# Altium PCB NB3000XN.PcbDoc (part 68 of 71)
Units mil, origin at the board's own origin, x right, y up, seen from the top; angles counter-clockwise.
Board outline 9527.56 x 6929.77 mil, 6 copper layers (Top Layer, GND+SHIELD, MidLayer1, MidLayer2, P2 - 3V3+5V0, Bottom Layer), stack 62.375 mil thick; 832 components, 1027 nets, 4655 pads, 4981 vias.
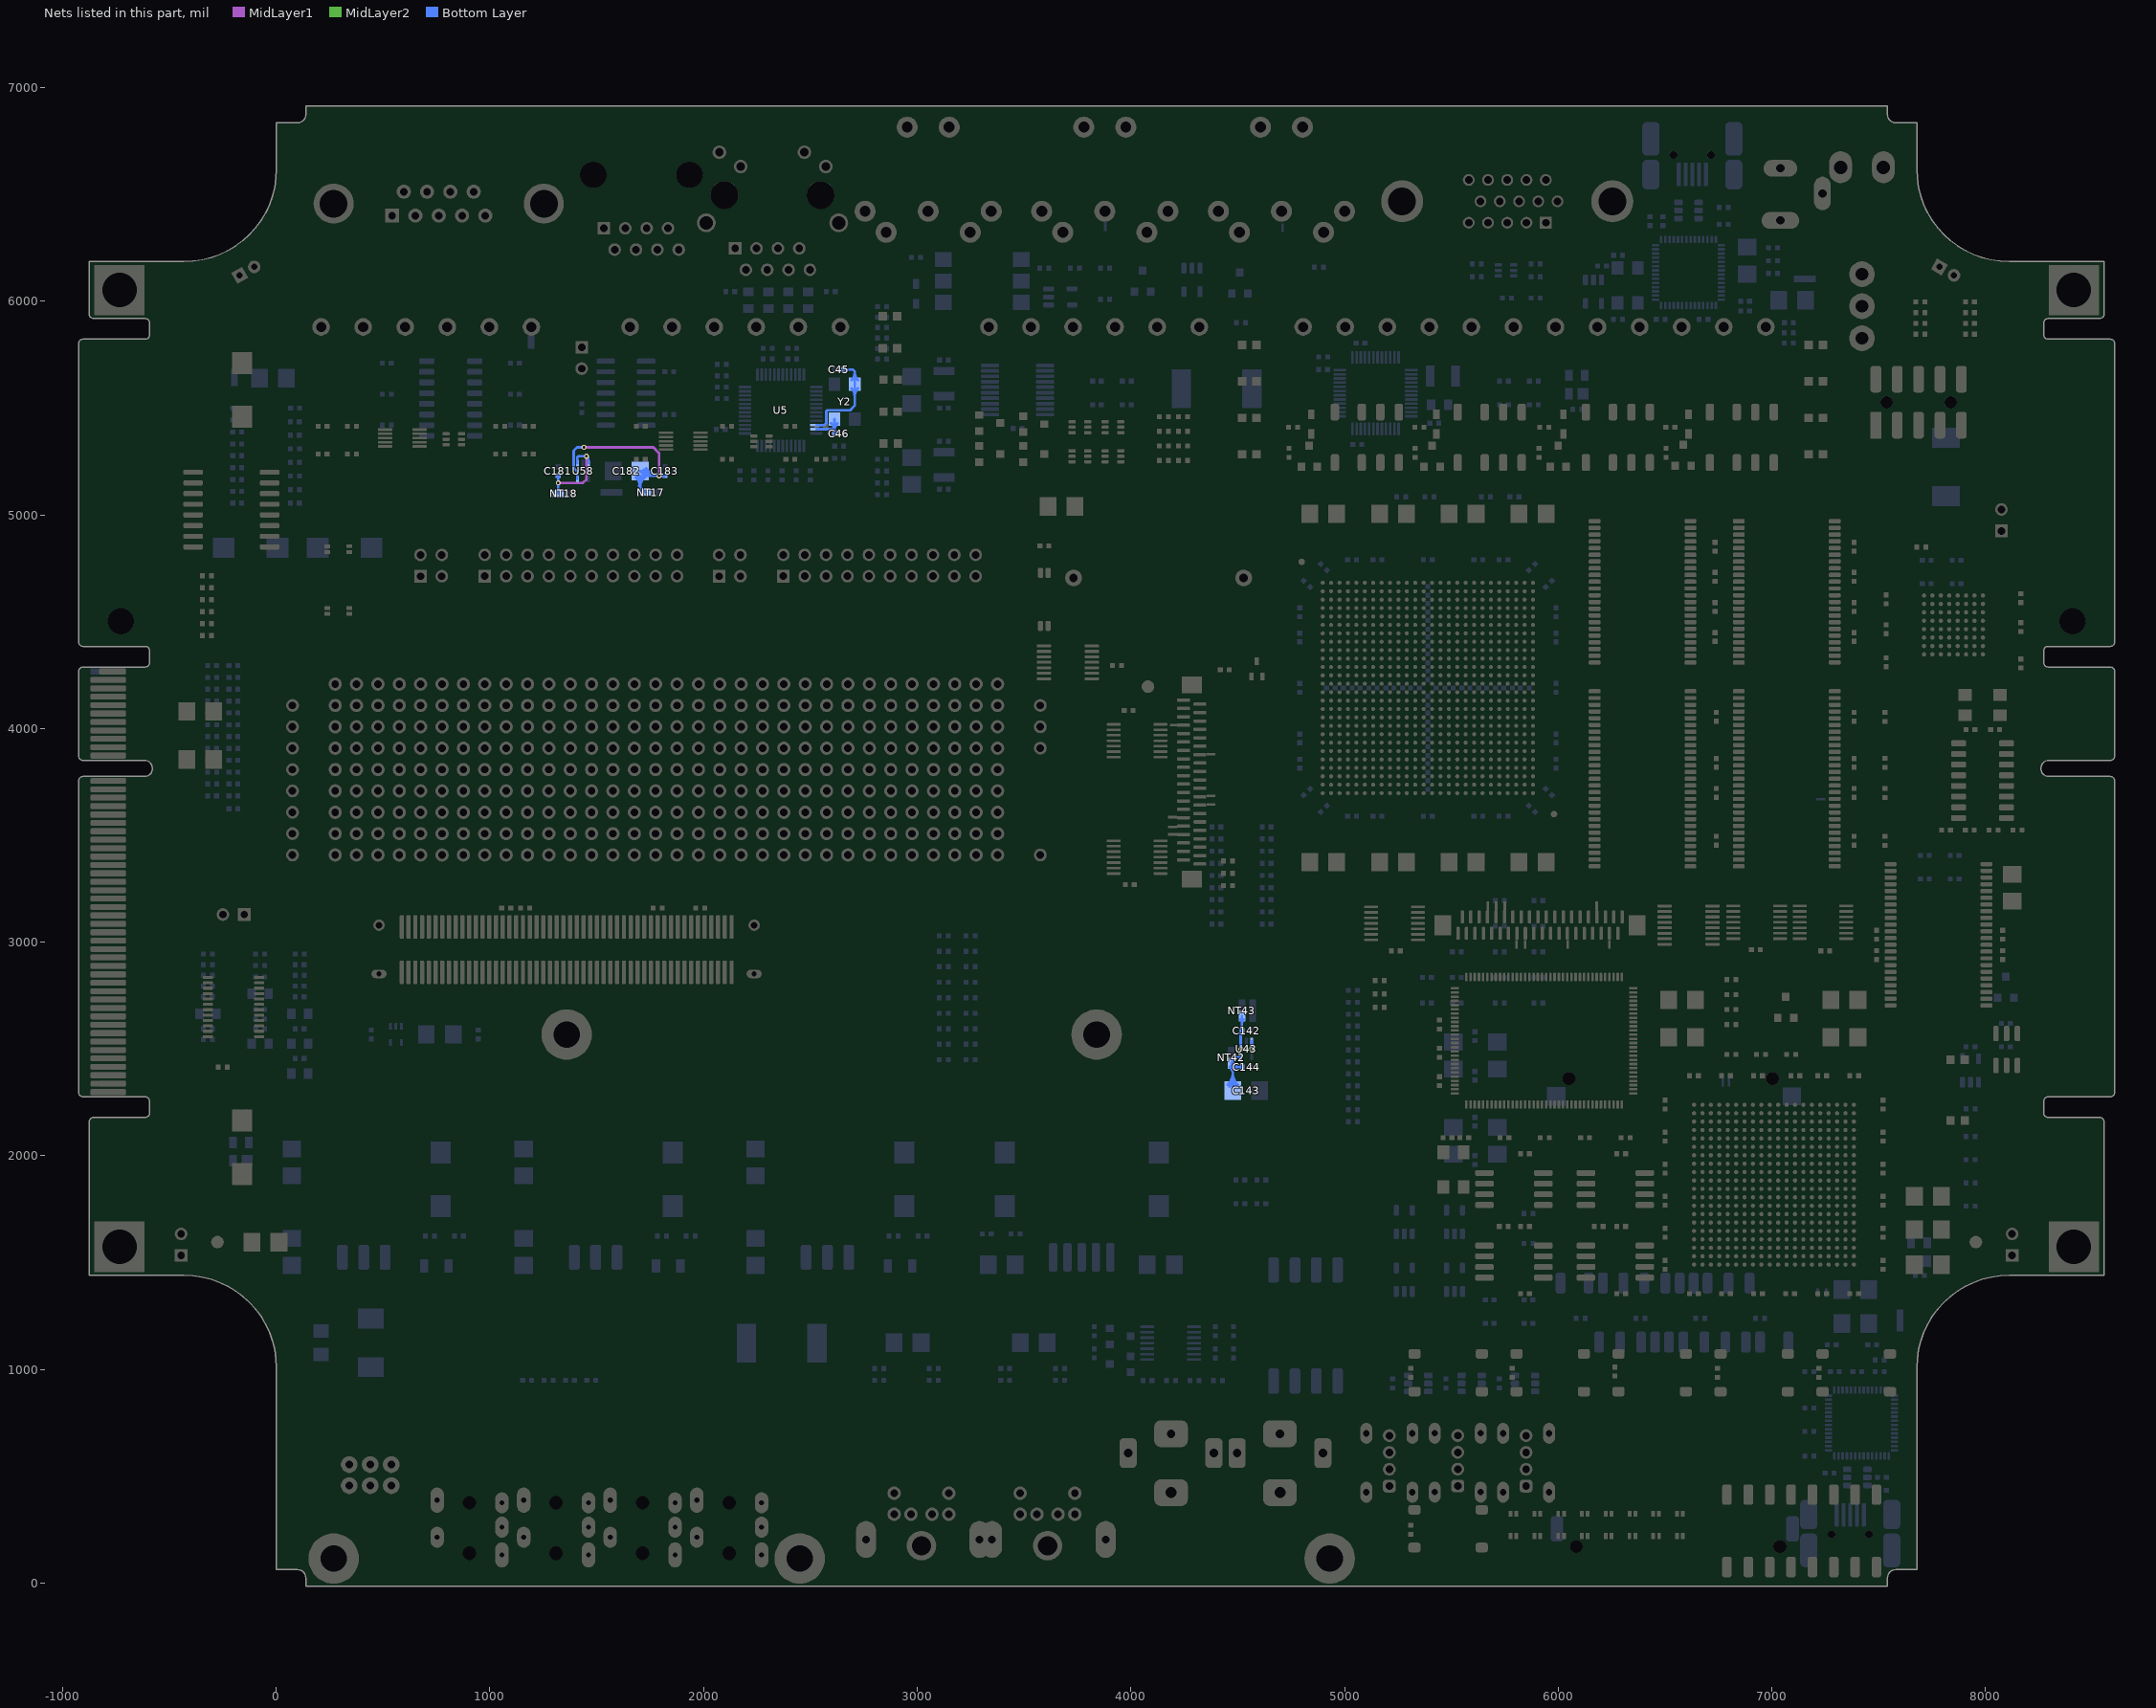
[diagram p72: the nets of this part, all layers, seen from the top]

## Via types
v1: diameter 23, hole 11.81, Top Layer to Bottom Layer, 3672 vias
v2: diameter 26, hole 11.81, Top Layer to Bottom Layer, 461 vias
v3: diameter 19, hole 11.81, Top Layer to Bottom Layer, tented both sides, 396 vias
v4: diameter 23.62, hole 11.81, Top Layer to Bottom Layer, 288 vias
v5: diameter 20, hole 11.81, Top Layer to Bottom Layer, 91 vias
v6: diameter 23, hole 11.81, Top Layer to Bottom Layer, tented both sides, 50 vias
v7: diameter 31, hole 11.81, Top Layer to Bottom Layer, 15 vias
v8: diameter 27.56, hole 11.81, Top Layer to Bottom Layer, tented both sides, 4 vias
v9: diameter 29, hole 11.81, Top Layer to Bottom Layer, 3 vias
v10: diameter 21, hole 11.81, Top Layer to Bottom Layer, 1 vias

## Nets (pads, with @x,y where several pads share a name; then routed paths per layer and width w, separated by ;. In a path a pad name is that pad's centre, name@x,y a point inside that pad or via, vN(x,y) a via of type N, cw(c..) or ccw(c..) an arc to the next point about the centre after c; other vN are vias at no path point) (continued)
VINA: C142.2 NT43.1 U43.1 U43.3 | length 405.5
  MidLayer2 w12: v1(4515.19,2500.04) v1(4565.19,2500.04) ; v1@4519.08,2496.15 cw(c4528.47,2486.76) 4528.47,2500.04 cw(c4528.47,2513.32) v1@4519.08,2503.93 ; v1@4561.3,2496.15 ccw(c4551.91,2486.76) 4551.91,2500.04 ccw(c4551.91,2513.32) v1@4561.3,2503.93
  Bottom Layer w12: NT43.1@4513.34,2637.78 cw(c4496.7,2621.14) 4520.24,2621.14 cw(c4543.77,2621.14) NT43.1@4527.13,2637.78 ; 4514.41,2515.2 ccw(c4530.35,2515.2) v1@4519.08,2503.93 ; 4514.41,2556.71 cw(c4548.6,2556.71) C142.2@4524.42,2580.89 ; v1(4515.19,2500.04) 4514.41,2500.82 U43.1@4514.41,2537.4 4514.41,2579.25 4520.24,2585.08 NT43.1@4520.24,2654.92 ; C142.2@4516.21,2589.11 ccw(c4506.48,2598.84) 4520.24,2598.84 ; 4520.24,2599.22 ccw(c4534.53,2599.22) C142.2@4524.42,2589.11 ; v1@4561.3,2503.93 ccw(c4550.95,2514.29) 4565.59,2514.29 ; v1@4565.59,2500.44 U43.3@4565.59,2537.4 ; 4565.59,2512.35 ccw(c4577.5,2512.35) v1@4569.08,2503.93
VINB: C181.2 NT18.1 U58.1 U58.3 | length 636.3
  MidLayer1 w12: v1(1319.92,5150.04) 1435.04,5150.04 1452.19,5167.19 v1(1452.19,5275.04) ; v1@1323.81,5146.15 cw(c1333.2,5136.76) 1333.2,5150.04 cw(c1333.2,5163.32) v1@1323.81,5153.93 ; v1@1448.3,5271.15 cw(c1438.91,5261.76) 1452.19,5261.76 cw(c1465.47,5261.76) v1@1456.08,5271.15
  Bottom Layer w12: NT18.1@1313.03,5106.66 ccw(c1296.2,5123.49) 1320,5123.49 ; C181.2@1315.89,5180.22 cw(c1305.97,5170.3) 1320,5170.3 cw(c1334.03,5170.3) C181.2@1324.11,5180.22 ; v1@1316.03,5146.15 cw(c1306.45,5136.57) 1320,5136.57 ; v1@1316.03,5153.93 ccw(c1306.45,5163.51) 1320,5163.51 ; NT18.1@1319.92,5099.76 1320,5099.84 1320,5150.04 C181.2@1320,5184.33 ; 1320,5123.11 ccw(c1343.27,5123.11) NT18.1@1326.81,5106.66 ; 1320,5136.95 cw(c1333.01,5136.95) v1@1323.81,5146.15 ; 1320,5163.13 ccw(c1333.01,5163.13) v1@1323.81,5153.93 ; U58.1@1409.41,5242.4 1409.41,5269.41 1415.04,5275.04 v1(1452.19,5275.04) 1460.59,5266.64 U58.3@1460.59,5242.4 ; v1@1448.3,5278.93 cw(c1438.91,5288.32) 1438.91,5275.04 cw(c1438.91,5261.76) 1448.3,5271.15 cw(c1418.63,5241.48) U58.3@1460.59,5241.48
VOUTA: C143.1 C144.2 NT42.2 U43.5 | length 639.8
  Bottom Layer w12: C143.1@4453.41,2332.53 ccw(c4396.45,2389.5) 4477.01,2389.5 ccw(c4557.57,2389.5) C143.1@4500.6,2332.53 ; C143.1@4461.9,2324.05 ccw(c4425.42,2360.53) 4477.01,2360.53 ccw(c4528.6,2360.53) C143.1@4492.12,2324.05 ; NT42.2@4462.87,2416.75 cw(c4428.74,2382.62) 4477.01,2382.62 ; NT42.2@4468.17,2422.05 ccw(c4485.2,2439.08) NT42.2@4485.2,2415 ; NT42.2@4470,2433.37 4488.37,2415 ; NT42.2@4471.29,2453.78 ccw(c4476.23,2484.83) 4498.46,2462.6 ; NT42.2@4473.11,2414.49 cw(c4479.73,2396.39) 4493.36,2410.02 ; NT42.2@4476.66,2430.54 ccw(c4514.17,2468.05) C144.2@4514.17,2415 ; C143.1@4477.01,2305 4477.01,2426.65 NT42.2@4469.76,2433.9 4498.46,2462.6 ; NT42.2@4479.51,2423.76 ccw(c4488.37,2423.86) 4488.37,2415 ; U43.5@4514.41,2462.6 4498.46,2462.6 ; C144.2@4516.21,2410.89 ccw(c4506.29,2400.97) 4506.29,2415 ccw(c4506.29,2429.03) C144.2@4516.21,2419.11 ; C144.2@4520.31,2415 4488.37,2415
VOUTB: C182.1 C183.2 NT17.2 U58.5 | length 1382.6
  MidLayer1 w12: v1(1440.19,5316.71) 1765.15,5316.71 1791.86,5290 v1(1791.86,5183.37) ; v1@1444.08,5312.82 cw(c1453.47,5303.43) 1453.47,5316.71 cw(c1453.47,5329.99) v1@1444.08,5320.6 ; v1@1787.97,5187.26 ccw(c1778.58,5196.65) 1791.86,5196.65 ccw(c1805.14,5196.65) v1@1795.75,5187.26
  Bottom Layer w12: U58.5@1409.41,5167.6 1409.41,5203.14 1392.52,5220.03 1392.52,5300.94 1408.29,5316.71 v1(1440.19,5316.71) ; v1@1436.3,5312.82 ccw(c1426.91,5303.43) 1426.91,5316.71 ccw(c1426.91,5329.99) v1@1436.3,5320.6 ; C182.1@1682.36,5175.23 cw(c1645.89,5130.65) 1703.48,5130.65 ; C182.1@1689.95,5184.52 cw(c1666.6,5155.97) 1703.48,5155.97 cw(c1740.37,5155.97) C182.1@1717.01,5184.52 ; 1698.36,5135.77 cw(c1672.38,5109.79) NT17.2@1708.94,5106.19 ; C182.1@1703.48,5183.37 1703.48,5130.65 ; C182.1@1703.48,5205 1724.15,5184.33 v1@1791.86,5184.33 ; C182.1@1711.52,5205.87 ccw(c1749.52,5228.61) 1749.52,5184.33 ; C182.1@1721.82,5212.04 ccw(c1770.69,5241.28) 1770.69,5184.33 ; C182.1@1724.61,5175.23 ccw(c1761.08,5130.65) 1703.48,5130.65 ; C182.1@1727.08,5177.47 cw(c1743.65,5160.9) 1743.65,5184.33 ; NT17.2@1728.9,5105.24 1703.48,5130.65 ; C182.1@1732.12,5218.2 ccw(c1791.85,5253.95) v1@1791.85,5184.33 ; 1776.27,5184.33 cw(c1776.27,5167.79) v1@1787.97,5179.49 ; v1@1795.75,5179.49 cw(c1807.44,5167.79) 1807.44,5184.33 ; C183.2@1815.89,5180.22 ccw(c1805.97,5170.3) 1805.97,5184.33 ccw(c1805.97,5198.36) C183.2@1815.89,5188.44 ; C183.2@1820,5184.33 v1@1791.86,5184.33
X1: C45.2 U5.46 Y2.1 | length 649.5
  Bottom Layer w12: U5.46@2528.19,5421.1 2566.1,5421.1 2575,5430 2575,5484.85 2580.15,5490 2685.85,5490 2707.5,5511.65 Y2.1@2707.5,5611.5 2707.5,5672 2699.5,5680 C45.2@2655.67,5680 ; C45.2@2659.78,5675.89 cw(c2669.7,5665.97) 2669.7,5680 cw(c2669.7,5694.03) C45.2@2659.78,5684.11 ; Y2.1@2692.3,5592.3 cw(c2655.59,5555.59) 2707.5,5555.59 cw(c2759.41,5555.59) Y2.1@2722.7,5592.3 ; Y2.1@2692.3,5630.7 ccw(c2655.59,5667.41) 2707.5,5667.41 ccw(c2759.41,5667.41) Y2.1@2722.7,5630.7
X2: C46.2 U5.47 Y2.3 | length 251.3
  Bottom Layer w12: U5.47@2528.19,5401.42 2610.17,5401.42 2612,5399.59 ; Y2.3@2597.3,5429.3 cw(c2560.59,5392.59) 2612.5,5392.59 cw(c2664.41,5392.59) Y2.3@2627.7,5429.3 ; 2612.5,5398.45 ccw(c2632.78,5398.45) C46.2@2618.44,5384.11 ; Y2.3@2612.5,5448.5 2612.5,5381.83 C46.2@2614.33,5380
pads on no net: D1.2 D2.2 D7.3 FD1.0 FD2.0 FD3.0 J4.12 J4.13 J5.10 J5.11 J5.12 J5.13 J6.10 J6.12 J6.13 J7.12 J7.13 J8.7 J8.MH3 J8.MH4 J9.4 J9.X J9.Y J10.4 J10.X J10.Y J20.1 J20.2 J20.3 J21.1 J21.3 J22.1 J22.3 J23.4 J23.5 J23.7 J23.8 J23.MH1 J23.MH2 J25.PEGA J25.PEGB J27.41 J27.42 J28.41 J28.42 J29.MH1 J29.MH2 J30.MH1 J30.MH2 J31.2 J31.6 J32.2 J32.6 PROTOTYPE1.7 PROTOTYPE1.8 PROTOTYPE1.9 PROTOTYPE1.10 PROTOTYPE1.11 PROTOTYPE1.12 PROTOTYPE1.13 PROTOTYPE1.14 PROTOTYPE1.15 PROTOTYPE1.16 PROTOTYPE1.17 PROTOTYPE1.18 PROTOTYPE1.19 PROTOTYPE1.20 PROTOTYPE1.21 PROTOTYPE1.22 PROTOTYPE1.23 PROTOTYPE1.24 PROTOTYPE1.25 PROTOTYPE1.26 PROTOTYPE1.A2 PROTOTYPE1.A3 PROTOTYPE1.A4 PROTOTYPE1.A5 PROTOTYPE1.A6 PROTOTYPE1.A7 PROTOTYPE1.A8 PROTOTYPE1.A9 PROTOTYPE1.A10 PROTOTYPE1.A11 PROTOTYPE1.A12 PROTOTYPE1.A13 PROTOTYPE1.A14 PROTOTYPE1.A15 PROTOTYPE1.A16 PROTOTYPE1.A17 PROTOTYPE1.A18 PROTOTYPE1.A19 PROTOTYPE1.A20 PROTOTYPE1.A21 PROTOTYPE1.A22 PROTOTYPE1.A23 PROTOTYPE1.A24 PROTOTYPE1.A25 PROTOTYPE1.A26 PROTOTYPE1.A27 PROTOTYPE1.A28 PROTOTYPE1.A29 PROTOTYPE1.A30 PROTOTYPE1.A31 PROTOTYPE1.B2 PROTOTYPE1.B3 PROTOTYPE1.B4 PROTOTYPE1.B5 PROTOTYPE1.B6 PROTOTYPE1.B7 PROTOTYPE1.B8 PROTOTYPE1.B9 PROTOTYPE1.B10 PROTOTYPE1.B11 PROTOTYPE1.B12 PROTOTYPE1.B13 PROTOTYPE1.B14 PROTOTYPE1.B15 PROTOTYPE1.B16 PROTOTYPE1.B17 PROTOTYPE1.B18 PROTOTYPE1.B19 PROTOTYPE1.B20 PROTOTYPE1.B21 PROTOTYPE1.B22 PROTOTYPE1.B23 PROTOTYPE1.B24 PROTOTYPE1.B25 PROTOTYPE1.B26 PROTOTYPE1.B27 PROTOTYPE1.B28 PROTOTYPE1.B29 PROTOTYPE1.B30 PROTOTYPE1.B31 PROTOTYPE1.C1 PROTOTYPE1.C2 PROTOTYPE1.C3 PROTOTYPE1.C4 PROTOTYPE1.C5 PROTOTYPE1.C6 PROTOTYPE1.C7 PROTOTYPE1.C8 PROTOTYPE1.C9 PROTOTYPE1.C10 PROTOTYPE1.C11 PROTOTYPE1.C12 PROTOTYPE1.C13 PROTOTYPE1.C14 PROTOTYPE1.C15 PROTOTYPE1.C16 PROTOTYPE1.C17 PROTOTYPE1.C18 PROTOTYPE1.C19 PROTOTYPE1.C20 PROTOTYPE1.C21 PROTOTYPE1.C22 PROTOTYPE1.C23 PROTOTYPE1.C24 PROTOTYPE1.C25 PROTOTYPE1.C26 PROTOTYPE1.C27 PROTOTYPE1.C28 PROTOTYPE1.C29 PROTOTYPE1.C30 PROTOTYPE1.C31 PROTOTYPE1.C32 PROTOTYPE1.D1 PROTOTYPE1.D2 PROTOTYPE1.D3 PROTOTYPE1.D4 PROTOTYPE1.D5 PROTOTYPE1.D6 PROTOTYPE1.D7 PROTOTYPE1.D8 PROTOTYPE1.D9 PROTOTYPE1.D10 PROTOTYPE1.D11 PROTOTYPE1.D12 PROTOTYPE1.D13 PROTOTYPE1.D14 PROTOTYPE1.D15 PROTOTYPE1.D16 PROTOTYPE1.D17 PROTOTYPE1.D18 PROTOTYPE1.D19 PROTOTYPE1.D20 PROTOTYPE1.D21 PROTOTYPE1.D22 PROTOTYPE1.D23 PROTOTYPE1.D24 PROTOTYPE1.D25 PROTOTYPE1.D26 PROTOTYPE1.D27 PROTOTYPE1.D28 PROTOTYPE1.D29 PROTOTYPE1.D30 PROTOTYPE1.D31 PROTOTYPE1.D32 PROTOTYPE1.E1 PROTOTYPE1.E2 PROTOTYPE1.E3 PROTOTYPE1.E4 PROTOTYPE1.E5 PROTOTYPE1.E6 PROTOTYPE1.E7 PROTOTYPE1.E8 PROTOTYPE1.E9 PROTOTYPE1.E10 PROTOTYPE1.E11 PROTOTYPE1.E12 PROTOTYPE1.E13 PROTOTYPE1.E14 PROTOTYPE1.E15 PROTOTYPE1.E16 PROTOTYPE1.E17 PROTOTYPE1.E18 PROTOTYPE1.E19 PROTOTYPE1.E20 PROTOTYPE1.E21 PROTOTYPE1.E22 PROTOTYPE1.E23 PROTOTYPE1.E24 PROTOTYPE1.E25 PROTOTYPE1.E26 PROTOTYPE1.E27 PROTOTYPE1.E28 PROTOTYPE1.E29 PROTOTYPE1.E30 PROTOTYPE1.E31 PROTOTYPE1.E32 PROTOTYPE1.F1 PROTOTYPE1.F2 PROTOTYPE1.F3 PROTOTYPE1.F4 PROTOTYPE1.F5 PROTOTYPE1.F6 PROTOTYPE1.F7 PROTOTYPE1.F8 PROTOTYPE1.F9 PROTOTYPE1.F10 PROTOTYPE1.F11 PROTOTYPE1.F12 PROTOTYPE1.F13 PROTOTYPE1.F14 PROTOTYPE1.F15 PROTOTYPE1.F16 PROTOTYPE1.F17 PROTOTYPE1.F18 PROTOTYPE1.F19 PROTOTYPE1.F20 PROTOTYPE1.F21 PROTOTYPE1.F22 PROTOTYPE1.F23 PROTOTYPE1.F24 PROTOTYPE1.F25 PROTOTYPE1.F26 PROTOTYPE1.F27 PROTOTYPE1.F28 PROTOTYPE1.F29 PROTOTYPE1.F30 PROTOTYPE1.F31 PROTOTYPE1.F32 PROTOTYPE1.G1 PROTOTYPE1.G2 PROTOTYPE1.G3 PROTOTYPE1.G4 PROTOTYPE1.G5 PROTOTYPE1.G6 PROTOTYPE1.G7 PROTOTYPE1.G8 PROTOTYPE1.G9 PROTOTYPE1.G10 PROTOTYPE1.G11 PROTOTYPE1.G12 PROTOTYPE1.G13 PROTOTYPE1.G14 PROTOTYPE1.G15 PROTOTYPE1.G16 PROTOTYPE1.G17 PROTOTYPE1.G18 PROTOTYPE1.G19 PROTOTYPE1.G20 PROTOTYPE1.G21 PROTOTYPE1.G22 PROTOTYPE1.G23 PROTOTYPE1.G24 PROTOTYPE1.G25 PROTOTYPE1.G26 PROTOTYPE1.G27 PROTOTYPE1.G28 PROTOTYPE1.G29 PROTOTYPE1.G30 PROTOTYPE1.G31 PROTOTYPE1.G32 SW1.1 SW1.4 SW2.1 SW2.4 SW3.1 SW3.4 SW4.1 SW4.4 SW5.1 SW5.4 T1.2 T1.3 T1.6 T1.7 U2.2 U2.4 U2.7 U2.10 U2.14 U2.15 U3.6 U3.12 U4.1 U5.27 U6.3 U6.5 U6.7 U6.9 U6.16 U6.18 U7.A1 U7.A8 U7.B1 U7.B4 U7.C1 U7.D1 U7.E1 U7.F8 U7.G1 U7.G8 U7.H1 U7.H8 U8.A13 U8.A17 U8.A23 U8.A24 U8.AA4 U8.AA5 U8.AA8 U8.AB3 U8.AC5 U8.AC22 U8.AD5 U8.AD16 U8.AD23 U8.AE1 U8.B24 U8.B25 U8.D5 U8.D12 U8.D14 U8.D15 U8.D19 U8.E6 U8.E9 U8.E11 U8.E12 U8.E18 U8.E20 U8.F9 U8.F10 U8.F18 U8.FID1 U8.G11 U8.G14 U8.G16 U8.G18 U8.G25 U8.G26 U8.H13 U8.H18 U8.H23 U8.H24 U8.H25 U8.H26 U8.J3 U8.J10 U8.J13 U8.J15 U8.J17 U8.K24 U8.L23 U8.M24 U8.N23 U8.N25 U8.N26 U8.R23 U8.U25 U8.U26 U8.V26 U8.W18 U8.Y3 U8.Y4 U8.Y8 U8.Y11 U8.Y16 U8.Y18 U8.Y19 U12.40 U13.40 U18.3 U18.4 U19.54 U21.9 U21.10 U21.13 U21.14 U21.35 U21.36 U23.3 U23.5 U23.6 U27.3 U27.4 U27.11 U30.A15 U30.A16 U30.A17 U30.A18 U30.B15 U30.B17 U30.B18 U30.B19 U30.B20 U30.C14 U30.C15 U30.C16 U30.C17 U30.C19 U30.C20 U30.D12 U30.D14 U30.D15 U30.D16 U30.D17 U30.D18 U30.D20 U30.E13 U30.E14 U30.E15 U30.E18 U30.E19 U30.F11 U30.F12 U30.F13 U30.F14 U30.F16 U30.F17 U30.F18 U30.F19 U30.G6 U30.G7 U30.G8 U30.G9 U30.G10 U30.G11 U30.G12 U30.G13 U30.G14 U30.G15 U30.G16 U30.G17 U30.G18 U30.G20 U30.H7 U30.H9 U30.H10 U30.H11 U30.H12 U30.H14 U30.H15 U30.H17 U30.H18 U30.H19 U30.H20 U30.J7 U30.J8 U30.J13 U30.J14 U30.J15 U30.J16 U30.J17 U30.J18 U30.J19 U30.J20 U30.K5 U30.K6 U30.K7 U30.K8 U30.K14 U30.K15 U30.K16 U30.K18 U30.K20 U30.L6 U30.L7 U30.L13 U30.L14 U30.L15 U30.L16 U30.L17 U30.L18 U30.L19 U30.M6 U30.M7 U30.M8 U30.M13 U30.M14 U30.M15 U30.M16 U30.M17 U30.M18 U30.M19 U30.M20 U30.N6 U30.N7 U30.N9 U30.N12 U30.N14 U30.N15 U30.N17 U30.N18 U30.N19 U30.P5 U30.P6 U30.P7 U30.P8 U30.P9 U30.P10 U30.P11 U30.P12 U30.P13 U30.P14 U30.P15 U30.P16 U30.P17 U30.P18 U30.R8 U30.R10 U30.R14 U30.R16 U30.R17 U30.R18 U30.R19 U30.R20 U30.T11 U30.T18 U36.3 U36.6 U37.1 U38.1 U43.4 U44.4 U46.1 U46.8 U46.13 U54.1 U55.3 U55.4 U56.54 U58.4 U61.21 U61.28 U61.35 U61.111 U61.113 U62.3 U62.4 U63.3 U63.4 U64.3 U64.4 U65.1 U66.1 U67.1 U68.1 VR1.4 VR1.5 VR1.6
copper on no net: | length 31146.2
  Top Layer w4: 4870,3737.24 4897.87,3737.24 ; 4870,4391.03 4936.73,4391.03 cw(c4936.73,4352.35) 4964.08,4379.7 ; 4892.57,3731.94 ccw(c4879.77,3719.14) 4879.77,3737.24 ccw(c4879.77,3755.35) 4892.57,3742.55 ; 4892.68,3732.05 ccw(c4880.15,3719.52) 4880.15,3737.24 ccw(c4880.15,3754.97) 4892.68,3742.44 ; 4969.27,4367.17 ccw(c4951.55,4367.17) 4964.08,4379.7 ; 4976.61,4374.51 cw(c4976.61,4392.23) 4964.08,4379.7 ; v3(4996.3,3875.04) 5015.98,3894.72 ; v3(4996.3,3914.41) 5015.98,3934.09 ; 5008.48,3894.72 cw(c4990.38,3894.72) 5003.18,3881.92 cw(c5015.98,3869.12) 5015.98,3887.22 ; 5008.48,3934.09 cw(c4990.38,3934.09) 5003.18,3921.29 cw(c5015.98,3908.49) 5015.98,3926.59 ; 5008.64,3894.72 cw(c4990.92,3894.72) 5003.45,3882.19 cw(c5015.98,3869.66) 5015.98,3887.38 ; 5008.64,3934.09 cw(c4990.92,3934.09) 5003.45,3921.56 cw(c5015.98,3909.03) 5015.98,3926.75 ; v3(5035.67,3796.3) 5055.35,3815.98 ; v3(5035.67,3875.04) 5055.35,3894.72 ; v3(5035.67,4583.7) 5055.35,4564.02 ; 5047.85,3815.98 cw(c5029.75,3815.98) 5042.55,3803.18 cw(c5055.35,3790.38) 5055.35,3808.48 ; 5047.85,3894.72 cw(c5029.75,3894.72) 5042.55,3881.92 cw(c5055.35,3869.12) 5055.35,3887.22 ; 5047.85,4564.02 ccw(c5029.75,4564.02) 5042.55,4576.82 ccw(c5055.35,4589.62) 5055.35,4571.52 ; 5048.01,3815.98 cw(c5030.29,3815.98) 5042.82,3803.45 cw(c5055.35,3790.92) 5055.35,3808.64 ; 5048.01,3894.72 cw(c5030.29,3894.72) 5042.82,3882.19 cw(c5055.35,3869.66) 5055.35,3887.38 ; 5048.01,4564.02 ccw(c5030.29,4564.02) 5042.82,4576.55 ccw(c5055.35,4589.08) 5055.35,4571.36 ; v3(5075.04,4544.33) 5094.72,4524.65 ; 5087.22,4524.65 ccw(c5069.12,4524.65) 5081.92,4537.45 ccw(c5094.72,4550.25) 5094.72,4532.15 ; 5087.38,4524.65 ccw(c5069.66,4524.65) 5082.19,4537.18 ccw(c5094.72,4549.71) 5094.72,4531.99 ; v3(5153.78,3875.04) 5173.46,3894.72 ; v3(5153.78,3914.41) 5173.46,3934.09 ; 5165.96,3894.72 cw(c5147.86,3894.72) 5160.66,3881.92 cw(c5173.46,3869.12) 5173.46,3887.22 ; 5165.96,3934.09 cw(c5147.86,3934.09) 5160.66,3921.29 cw(c5173.46,3908.49) 5173.46,3926.59 ; 5166.12,3894.72 cw(c5148.4,3894.72) 5160.93,3882.19 cw(c5173.46,3869.66) 5173.46,3887.38 ; 5166.12,3934.09 cw(c5148.4,3934.09) 5160.93,3921.56 cw(c5173.46,3909.03) 5173.46,3926.75 ; v3(5193.15,4504.96) 5212.83,4485.28 ; v3(5193.15,4544.33) 5212.83,4524.65 ; 5205.33,4485.28 ccw(c5187.23,4485.28) 5200.03,4498.08 ccw(c5212.83,4510.88) 5212.83,4492.78 ; 5205.33,4524.65 ccw(c5187.23,4524.65) 5200.03,4537.45 ccw(c5212.83,4550.25) 5212.83,4532.15 ; 5205.49,4485.28 ccw(c5187.77,4485.28) 5200.3,4497.81 ccw(c5212.83,4510.34) 5212.83,4492.62 ; 5205.49,4524.65 ccw(c5187.77,4524.65) 5200.3,4537.18 ccw(c5212.83,4549.71) 5212.83,4531.99 ; v3(5232.52,4386.85) 5252.2,4367.17 ; v3(5232.52,4504.96) 5252.2,4485.28 ; 5244.7,4367.17 ccw(c5226.6,4367.17) 5239.4,4379.97 ccw(c5252.2,4392.77) 5252.2,4374.67 ; 5244.7,4485.28 ccw(c5226.6,4485.28) 5239.4,4498.08 ccw(c5252.2,4510.88) 5252.2,4492.78 ; 5244.86,4367.17 ccw(c5227.14,4367.17) 5239.67,4379.7 ccw(c5252.2,4392.23) 5252.2,4374.51 ; 5244.86,4485.28 ccw(c5227.14,4485.28) 5239.67,4497.81 ccw(c5252.2,4510.34) 5252.2,4492.62 ; v3(5271.89,3914.41) 5291.57,3934.09 ; v3(5271.89,4465.59) 5291.57,4445.91 ; v3(5271.89,4544.33) 5291.57,4524.65 ; 5284.07,3934.09 cw(c5265.97,3934.09) 5278.77,3921.29 cw(c5291.57,3908.49) 5291.57,3926.59 ; 5284.07,4445.91 ccw(c5265.97,4445.91) 5278.77,4458.71 ccw(c5291.57,4471.51) 5291.57,4453.41 ; 5284.07,4524.65 ccw(c5265.97,4524.65) 5278.77,4537.45 ccw(c5291.57,4550.25) 5291.57,4532.15 ; 5284.23,3934.09 cw(c5266.51,3934.09) 5279.04,3921.56 cw(c5291.57,3909.03) 5291.57,3926.75 ; 5284.23,4445.91 ccw(c5266.51,4445.91) 5279.04,4458.44 ccw(c5291.57,4470.97) 5291.57,4453.25 ; 5284.23,4524.65 ccw(c5266.51,4524.65) 5279.04,4537.18 ccw(c5291.57,4549.71) 5291.57,4531.99 ; v3(5311.26,4544.33) 5330.94,4524.65 ; v3(5311.26,4583.7) 5330.94,4564.02 ; 5323.44,4524.65 ccw(c5305.34,4524.65) 5318.14,4537.45 ccw(c5330.94,4550.25) 5330.94,4532.15 ; 5323.44,4564.02 ccw(c5305.34,4564.02) 5318.14,4576.82 ccw(c5330.94,4589.62) 5330.94,4571.52 ; 5323.6,4524.65 ccw(c5305.88,4524.65) 5318.41,4537.18 ccw(c5330.94,4549.71) 5330.94,4531.99 ; 5323.6,4564.02 ccw(c5305.88,4564.02) 5318.41,4576.55 ccw(c5330.94,4589.08) 5330.94,4571.36 ; v3(5350.63,4386.85) 5370.31,4367.17 ; v3(5350.63,4426.22) 5370.31,4406.54 ; 5362.81,4367.17 ccw(c5344.71,4367.17) 5357.51,4379.97 ccw(c5370.31,4392.77) 5370.31,4374.67 ; 5362.81,4406.54 ccw(c5344.71,4406.54) 5357.51,4419.34 ccw(c5370.31,4432.14) 5370.31,4414.04 ; 5362.97,4367.17 ccw(c5345.25,4367.17) 5357.78,4379.7 ccw(c5370.31,4392.23) 5370.31,4374.51 ; 5362.97,4406.54 ccw(c5345.25,4406.54) 5357.78,4419.07 ccw(c5370.31,4431.6) 5370.31,4413.88 ; 5365.01,4687.43 ccw(c5352.21,4700.23) 5370.31,4700.23 ccw(c5388.42,4700.23) 5375.62,4687.43 ; 5365.12,4687.32 ccw(c5352.59,4699.85) 5370.31,4699.85 ccw(c5388.04,4699.85) 5375.51,4687.32 ; 5370.31,4682.13 5370.31,4710 ; 5409.69,4445.91 v3(5429.37,4465.59) ; 5409.69,4453.25 ccw(c5409.69,4470.97) 5422.22,4458.44 ccw(c5434.75,4445.91) 5417.03,4445.91 ; 5409.69,4453.41 ccw(c5409.69,4471.51) 5422.49,4458.71 ccw(c5435.29,4445.91) 5417.19,4445.91 ; 5409.69,4564.02 v3(5429.37,4583.7) ; 5409.69,4571.36 ccw(c5409.69,4589.08) 5422.22,4576.55 ccw(c5434.75,4564.02) 5417.03,4564.02 ; 5409.69,4571.52 ccw(c5409.69,4589.62) 5422.49,4576.82 ccw(c5435.29,4564.02) 5417.19,4564.02 ; 5449.06,4367.17 v3(5468.74,4386.85) ; 5449.06,4374.51 ccw(c5449.06,4392.23) 5461.59,4379.7 ccw(c5474.12,4367.17) 5456.4,4367.17 ; 5449.06,4374.67 ccw(c5449.06,4392.77) 5461.86,4379.97 ccw(c5474.66,4367.17) 5456.56,4367.17 ; 5449.06,4564.02 v3(5468.74,4583.7) ; 5449.06,4571.36 ccw(c5449.06,4589.08) 5461.59,4576.55 ccw(c5474.12,4564.02) 5456.4,4564.02 ; 5449.06,4571.52 ccw(c5449.06,4589.62) 5461.86,4576.82 ccw(c5474.66,4564.02) 5456.56,4564.02 ; 5488.43,3769.27 cw(c5488.43,3751.55) 5500.96,3764.08 ; 5488.43,3926.59 cw(c5488.43,3908.49) 5501.23,3921.29 cw(c5514.03,3934.09) 5495.93,3934.09 ; 5488.43,3926.75 cw(c5488.43,3909.03) 5500.96,3921.56 cw(c5513.49,3934.09) 5495.77,3934.09 ; 5488.43,3934.09 v3(5508.11,3914.41) ; 5488.43,4445.91 v3(5508.11,4465.59) ; 5488.43,4453.25 ccw(c5488.43,4470.97) 5500.96,4458.44 ccw(c5513.49,4445.91) 5495.77,4445.91 ; 5488.43,4453.41 ccw(c5488.43,4471.51) 5501.23,4458.71 ccw(c5514.03,4445.91) 5495.93,4445.91 ; 5495.77,3776.61 ccw(c5513.49,3776.61) 5500.96,3764.08 ; 5512.29,3670 5512.29,3736.73 ccw(c5473.61,3736.73) 5500.96,3764.08 ; 5527.8,4367.17 v3(5547.48,4386.85) ; 5527.8,4374.51 ccw(c5527.8,4392.23) 5540.33,4379.7 ccw(c5552.86,4367.17) 5535.14,4367.17 ; 5527.8,4374.67 ccw(c5527.8,4392.77) 5540.6,4379.97 ccw(c5553.4,4367.17) 5535.3,4367.17 ; 5567.17,3926.59 cw(c5567.17,3908.49) 5579.97,3921.29 cw(c5592.77,3934.09) 5574.67,3934.09 ; 5567.17,3926.75 cw(c5567.17,3909.03) 5579.7,3921.56 cw(c5592.23,3934.09) 5574.51,3934.09 ; 5567.17,3934.09 v3(5586.85,3914.41) ; 5567.17,3965.96 cw(c5567.17,3947.86) 5579.97,3960.66 cw(c5592.77,3973.46) 5574.67,3973.46 ; 5567.17,3966.12 cw(c5567.17,3948.4) 5579.7,3960.93 cw(c5592.23,3973.46) 5574.51,3973.46 ; 5567.17,3973.46 v3(5586.85,3953.78) ; 5567.17,4406.54 v3(5586.85,4426.22) ; 5567.17,4413.88 ccw(c5567.17,4431.6) 5579.7,4419.07 ccw(c5592.23,4406.54) 5574.51,4406.54 ; 5567.17,4414.04 ccw(c5567.17,4432.14) 5579.97,4419.34 ccw(c5592.77,4406.54) 5574.67,4406.54 ; 5567.17,4445.91 v3(5586.85,4465.59) ; 5567.17,4453.25 ccw(c5567.17,4470.97) 5579.7,4458.44 ccw(c5592.23,4445.91) 5574.51,4445.91 ; 5567.17,4453.41 ccw(c5567.17,4471.51) 5579.97,4458.71 ccw(c5592.77,4445.91) 5574.67,4445.91 ; 5567.17,4485.28 v3(5586.85,4504.96) ; 5567.17,4492.62 ccw(c5567.17,4510.34) 5579.7,4497.81 ccw(c5592.23,4485.28) 5574.51,4485.28 ; 5567.17,4492.78 ccw(c5567.17,4510.88) 5579.97,4498.08 ccw(c5592.77,4485.28) 5574.67,4485.28 ; 5567.17,4524.65 v3(5586.85,4544.33) ; 5567.17,4531.99 ccw(c5567.17,4549.71) 5579.7,4537.18 ccw(c5592.23,4524.65) 5574.51,4524.65 ; 5567.17,4532.15 ccw(c5567.17,4550.25) 5579.97,4537.45 ccw(c5592.77,4524.65) 5574.67,4524.65 ; 5606.54,3926.59 cw(c5606.54,3908.49) 5619.34,3921.29 cw(c5632.14,3934.09) 5614.04,3934.09 ; 5606.54,3926.75 cw(c5606.54,3909.03) 5619.07,3921.56 cw(c5631.6,3934.09) 5613.88,3934.09 ; 5606.54,3934.09 v3(5626.22,3914.41) ; 5606.54,4564.02 v3(5626.22,4583.7) ; 5606.54,4571.36 ccw(c5606.54,4589.08) 5619.07,4576.55 ccw(c5631.6,4564.02) 5613.88,4564.02 ; 5606.54,4571.52 ccw(c5606.54,4589.62) 5619.34,4576.82 ccw(c5632.14,4564.02) 5614.04,4564.02 ; 5645.91,4524.65 v3(5665.59,4544.33) ; 5645.91,4531.99 ccw(c5645.91,4549.71) 5658.44,4537.18 ccw(c5670.97,4524.65) 5653.25,4524.65 ; 5645.91,4532.15 ccw(c5645.91,4550.25) 5658.71,4537.45 ccw(c5671.51,4524.65) 5653.41,4524.65 ; 5724.65,3808.48 cw(c5724.65,3790.38) 5737.45,3803.18 cw(c5750.25,3815.98) 5732.15,3815.98 ; 5724.65,3808.64 cw(c5724.65,3790.92) 5737.18,3803.45 cw(c5749.71,3815.98) 5731.99,3815.98 ; 5724.65,3815.98 v3(5744.33,3796.3) ; 5758.71,4687.43 ccw(c5745.91,4700.23) 5764.02,4700.23 ccw(c5782.12,4700.23) 5769.32,4687.43 ; 5758.82,4687.32 ccw(c5746.29,4699.85) 5764.02,4699.85 ccw(c5781.74,4699.85) 5769.21,4687.32 ; 5764.02,4123.44 cw(c5764.02,4105.34) 5776.82,4118.14 cw(c5789.62,4130.94) 5771.52,4130.94 ; 5764.02,4123.6 cw(c5764.02,4105.88) 5776.55,4118.41 cw(c5789.08,4130.94) 5771.36,4130.94 ; 5764.02,4130.94 v3(5783.7,4111.26) ; 5764.02,4209.69 v3(5783.7,4229.37) ; 5764.02,4217.03 ccw(c5764.02,4234.75) 5776.55,4222.22 ccw(c5789.08,4209.69) 5771.36,4209.69 ; 5764.02,4217.19 ccw(c5764.02,4235.29) 5776.82,4222.49 ccw(c5789.62,4209.69) 5771.52,4209.69 ; 5764.02,4288.43 v3(5783.7,4308.11) ; 5764.02,4295.77 ccw(c5764.02,4313.49) 5776.55,4300.96 ccw(c5789.08,4288.43) 5771.36,4288.43 ; 5764.02,4295.93 ccw(c5764.02,4314.03) 5776.82,4301.23 ccw(c5789.62,4288.43) 5771.52,4288.43 ; 5764.02,4406.54 v3(5783.7,4426.22) ; 5764.02,4413.88 ccw(c5764.02,4431.6) 5776.55,4419.07 ccw(c5789.08,4406.54) 5771.36,4406.54 ; 5764.02,4414.04 ccw(c5764.02,4432.14) 5776.82,4419.34 ccw(c5789.62,4406.54) 5771.52,4406.54 ; 5764.02,4682.13 5764.02,4710 ; 5798.08,4687.43 ccw(c5785.28,4700.23) 5803.39,4700.23 ccw(c5821.49,4700.23) 5808.69,4687.43 ; 5798.19,4687.32 ccw(c5785.66,4699.85) 5803.39,4699.85 ccw(c5821.11,4699.85) 5808.58,4687.32 ; 5803.39,4256.4 ccw(c5803.39,4274.12) 5815.92,4261.59 ; 5803.39,4413.88 ccw(c5803.39,4431.6) 5815.92,4419.07 ; 5803.39,4682.13 5803.39,4710 ; 5810.73,4249.06 cw(c5828.45,4249.06) 5815.92,4261.59 ; 5810.73,4406.54 cw(c5828.45,4406.54) 5815.92,4419.07 ; 5842.76,4217.03 ccw(c5842.76,4234.75) 5855.29,4222.22 ; 5842.76,4413.88 ccw(c5842.76,4431.6) 5855.29,4419.07 ; 5850.1,4209.69 cw(c5867.83,4209.69) 5855.29,4222.22 ; 5850.1,4406.54 cw(c5867.83,4406.54) 5855.29,4419.07 ; 5882.13,4012.83 5910,4012.83 ; 5882.13,4209.69 5910,4209.69 ; 5882.13,4406.54 5910,4406.54 ; 5887.32,4007.64 cw(c5899.85,3995.11) 5899.85,4012.83 cw(c5899.85,4030.56) 5887.32,4018.03 ; 5887.32,4204.49 cw(c5899.85,4191.96) 5899.85,4209.69 cw(c5899.85,4227.41) 5887.32,4214.88 ; 5887.32,4401.34 cw(c5899.85,4388.81) 5899.85,4406.54 cw(c5899.85,4424.26) 5887.32,4411.73 ; 5887.43,4007.53 cw(c5900.23,3994.73) 5900.23,4012.83 cw(c5900.23,4030.94) 5887.43,4018.14 ; 5887.43,4204.38 cw(c5900.23,4191.58) 5900.23,4209.69 cw(c5900.23,4227.79) 5887.43,4214.99 ; 5887.43,4401.23 cw(c5900.23,4388.43) 5900.23,4406.54 cw(c5900.23,4424.64) 5887.43,4411.84 ; 5910,4225.19 5862.47,4225.19 ccw(c5862.47,4215.04) 5855.29,4222.22 ; 5910,4272.92 5843.27,4272.92 ccw(c5843.27,4234.24) 5815.92,4261.59 ; 5910,4422.04 5862.47,4422.04 ccw(c5862.47,4411.89) 5855.29,4419.07 ; 5910,4430.4 5843.27,4430.4 ccw(c5843.27,4391.72) 5815.92,4419.07 ; 4936.73,3831.49 ccw(c4936.73,3870.17) 4964.08,3842.82 ; 4936.73,3831.49 ccw(c4936.73,3870.17) 4964.08,3842.82 ; 4936.73,3831.49 4870,3831.49 4936.73,3831.49 ; 4936.73,3910.23 ccw(c4936.73,3948.91) 4964.08,3921.56 ; 4936.73,3910.23 ccw(c4936.73,3948.91) 4964.08,3921.56 ; 4936.73,3910.23 4870,3910.23 4936.73,3910.23 ; 4964.08,3842.82 cw(c4976.61,3830.29) 4976.61,3848.01 ccw(c4976.61,3830.29) 4964.08,3842.82 ; 4964.08,3842.82 ccw(c4951.55,3855.35) 4969.27,3855.35 cw(c4951.55,3855.35) 4964.08,3842.82 ; 4964.08,3921.56 cw(c4976.61,3909.03) 4976.61,3926.75 ccw(c4976.61,3909.03) 4964.08,3921.56 ; 4964.08,3921.56 ccw(c4951.55,3934.09) 4969.27,3934.09 cw(c4951.55,3934.09) 4964.08,3921.56 ; 5009.1,3887.84 ccw(c5021.91,3875.04) 5003.8,3875.04 cw(c5021.91,3875.04) 5009.1,3887.84 ; 5009.1,3887.84 cw(c4996.3,3900.65) 4996.3,3882.54 ccw(c4996.3,3900.65) 5009.1,3887.84 ; 5009.1,3927.21 cw(c4996.3,3940.02) 4996.3,3921.91 ccw(c4996.3,3940.02) 5009.1,3927.21 ; 5009.1,3927.21 ccw(c5021.91,3914.41) 5003.8,3914.41 cw(c5021.91,3914.41) 5009.1,3927.21 ; 5031.49,3736.73 cw(c5070.17,3736.73) 5042.82,3764.08 ; 5031.49,3736.73 cw(c5070.17,3736.73) 5042.82,3764.08 ; 5031.49,3736.73 5031.49,3670 5031.49,3736.73 ; 5042.82,3764.08 ccw(c5030.29,3776.61) 5048.01,3776.61 cw(c5030.29,3776.61) 5042.82,3764.08 ; 5042.82,3764.08 cw(c5055.35,3751.55) 5055.35,3769.27 ccw(c5055.35,3751.55) 5042.82,3764.08 ; 5048.47,3809.1 cw(c5035.67,3821.91) 5035.67,3803.8 ccw(c5035.67,3821.91) 5048.47,3809.1 ; 5048.47,3809.1 ccw(c5061.28,3796.3) 5043.17,3796.3 cw(c5061.28,3796.3) 5048.47,3809.1 ; 5048.47,3887.84 cw(c5035.67,3900.65) 5035.67,3882.54 ccw(c5035.67,3900.65) 5048.47,3887.84 ; 5048.47,3887.84 ccw(c5061.28,3875.04) 5043.17,3875.04 cw(c5061.28,3875.04) 5048.47,3887.84 ; 5048.47,4570.9 ccw(c5035.67,4558.09) 5035.67,4576.2 cw(c5035.67,4558.09) 5048.47,4570.9 ; 5048.47,4570.9 cw(c5061.28,4583.7) 5043.17,4583.7 ccw(c5061.28,4583.7) 5048.47,4570.9 ; 5087.84,4531.53 cw(c5100.65,4544.33) 5082.54,4544.33 ccw(c5100.65,4544.33) 5087.84,4531.53 ; 5087.84,4531.53 ccw(c5075.04,4518.72) 5075.04,4536.83 cw(c5075.04,4518.72) 5087.84,4531.53 ; 5166.58,3887.84 ccw(c5179.39,3875.04) 5161.28,3875.04 cw(c5179.39,3875.04) 5166.58,3887.84 ; 5166.58,3887.84 cw(c5153.78,3900.65) 5153.78,3882.54 ccw(c5153.78,3900.65) 5166.58,3887.84 ; 5166.58,3927.21 cw(c5153.78,3940.02) 5153.78,3921.91 ccw(c5153.78,3940.02) 5166.58,3927.21 ; 5166.58,3927.21 ccw(c5179.39,3914.41) 5161.28,3914.41 cw(c5179.39,3914.41) 5166.58,3927.21 ; 5205.95,4492.16 ccw(c5193.15,4479.35) 5193.15,4497.46 cw(c5193.15,4479.35) 5205.95,4492.16 ; 5205.95,4492.16 cw(c5218.76,4504.96) 5200.65,4504.96 ccw(c5218.76,4504.96) 5205.95,4492.16 ; 5205.95,4531.53 ccw(c5193.15,4518.72) 5193.15,4536.83 cw(c5193.15,4518.72) 5205.95,4531.53 ; 5205.95,4531.53 cw(c5218.76,4544.33) 5200.65,4544.33 ccw(c5218.76,4544.33) 5205.95,4531.53 ; 5245.32,4374.05 cw(c5258.13,4386.85) 5240.02,4386.85 ccw(c5258.13,4386.85) 5245.32,4374.05 ; 5245.32,4374.05 ccw(c5232.52,4361.24) 5232.52,4379.35 cw(c5232.52,4361.24) 5245.32,4374.05 ; 5245.32,4492.16 cw(c5258.13,4504.96) 5240.02,4504.96 ccw(c5258.13,4504.96) 5245.32,4492.16 ; 5245.32,4492.16 ccw(c5232.52,4479.35) 5232.52,4497.46 cw(c5232.52,4479.35) 5245.32,4492.16 ; 5284.69,3927.21 cw(c5271.89,3940.02) 5271.89,3921.91 ccw(c5271.89,3940.02) 5284.69,3927.21 ; 5284.69,3927.21 ccw(c5297.5,3914.41) 5279.39,3914.41 cw(c5297.5,3914.41) 5284.69,3927.21 ; 5284.69,4452.79 cw(c5297.5,4465.59) 5279.39,4465.59 ccw(c5297.5,4465.59) 5284.69,4452.79 ; 5284.69,4452.79 ccw(c5271.89,4439.98) 5271.89,4458.09 cw(c5271.89,4439.98) 5284.69,4452.79 ; 5284.69,4531.53 cw(c5297.5,4544.33) 5279.39,4544.33 ccw(c5297.5,4544.33) 5284.69,4531.53 ; 5284.69,4531.53 ccw(c5271.89,4518.72) 5271.89,4536.83 cw(c5271.89,4518.72) 5284.69,4531.53 ; 5324.06,4531.53 cw(c5336.87,4544.33) 5318.76,4544.33 ccw(c5336.87,4544.33) 5324.06,4531.53 ; 5324.06,4531.53 ccw(c5311.26,4518.72) 5311.26,4536.83 cw(c5311.26,4518.72) 5324.06,4531.53 ; 5324.06,4570.9 cw(c5336.87,4583.7) 5318.76,4583.7 ccw(c5336.87,4583.7) 5324.06,4570.9 ; 5324.06,4570.9 ccw(c5311.26,4558.09) 5311.26,4576.2 cw(c5311.26,4558.09) 5324.06,4570.9 ; 5363.43,4374.05 cw(c5376.24,4386.85) 5358.13,4386.85 ccw(c5376.24,4386.85) 5363.43,4374.05 ; 5363.43,4374.05 ccw(c5350.63,4361.24) 5350.63,4379.35 cw(c5350.63,4361.24) 5363.43,4374.05 ; 5363.43,4413.42 cw(c5376.24,4426.22) 5358.13,4426.22 ccw(c5376.24,4426.22) 5363.43,4413.42 ; 5363.43,4413.42 ccw(c5350.63,4400.61) 5350.63,4418.72 cw(c5350.63,4400.61) 5363.43,4413.42 ; 5416.57,4452.79 cw(c5429.37,4439.98) 5429.37,4458.09 ccw(c5429.37,4439.98) 5416.57,4452.79 ; 5416.57,4452.79 ccw(c5403.76,4465.59) 5421.87,4465.59 cw(c5403.76,4465.59) 5416.57,4452.79 ; 5416.57,4570.9 cw(c5429.37,4558.09) 5429.37,4576.2 ccw(c5429.37,4558.09) 5416.57,4570.9 ; 5416.57,4570.9 ccw(c5403.76,4583.7) 5421.87,4583.7 cw(c5403.76,4583.7) 5416.57,4570.9 ; 5455.94,4374.05 cw(c5468.74,4361.24) 5468.74,4379.35 ccw(c5468.74,4361.24) 5455.94,4374.05 ; 5455.94,4374.05 ccw(c5443.13,4386.85) 5461.24,4386.85 cw(c5443.13,4386.85) 5455.94,4374.05 ; 5455.94,4570.9 cw(c5468.74,4558.09) 5468.74,4576.2 ccw(c5468.74,4558.09) 5455.94,4570.9 ; 5455.94,4570.9 ccw(c5443.13,4583.7) 5461.24,4583.7 cw(c5443.13,4583.7) 5455.94,4570.9 ; 5495.31,3927.21 cw(c5482.5,3914.41) 5500.61,3914.41 ccw(c5482.5,3914.41) 5495.31,3927.21 ; 5495.31,3927.21 ccw(c5508.11,3940.02) 5508.11,3921.91 cw(c5508.11,3940.02) 5495.31,3927.21 ; 5495.31,4452.79 cw(c5508.11,4439.98) 5508.11,4458.09 ccw(c5508.11,4439.98) 5495.31,4452.79 ; 5495.31,4452.79 ccw(c5482.5,4465.59) 5500.61,4465.59 cw(c5482.5,4465.59) 5495.31,4452.79 ; 5527.8,4699.85 ccw(c5545.52,4699.85) 5532.99,4687.32 cw(c5545.52,4699.85) 5527.8,4699.85 ; 5527.8,4699.85 cw(c5510.07,4699.85) 5522.6,4687.32 ccw(c5510.07,4699.85) 5527.8,4699.85 ; 5527.8,4700.23 cw(c5509.69,4700.23) 5522.49,4687.43 ccw(c5509.69,4700.23) 5527.8,4700.23 ; 5527.8,4700.23 ccw(c5545.9,4700.23) 5533.1,4687.43 cw(c5545.9,4700.23) 5527.8,4700.23 ; 5534.68,4374.05 cw(c5547.48,4361.24) 5547.48,4379.35 ccw(c5547.48,4361.24) 5534.68,4374.05 ; 5534.68,4374.05 ccw(c5521.87,4386.85) 5539.98,4386.85 cw(c5521.87,4386.85) 5534.68,4374.05 ; 5574.05,3927.21 cw(c5561.24,3914.41) 5579.35,3914.41 ccw(c5561.24,3914.41) 5574.05,3927.21 ; 5574.05,3927.21 ccw(c5586.85,3940.02) 5586.85,3921.91 cw(c5586.85,3940.02) 5574.05,3927.21 ; 5574.05,3966.58 cw(c5561.24,3953.78) 5579.35,3953.78 ccw(c5561.24,3953.78) 5574.05,3966.58 ; 5574.05,3966.58 ccw(c5586.85,3979.39) 5586.85,3961.28 cw(c5586.85,3979.39) 5574.05,3966.58 ; 5574.05,4413.42 cw(c5586.85,4400.61) 5586.85,4418.72 ccw(c5586.85,4400.61) 5574.05,4413.42 ; 5574.05,4413.42 ccw(c5561.24,4426.22) 5579.35,4426.22 cw(c5561.24,4426.22) 5574.05,4413.42 ; 5574.05,4452.79 cw(c5586.85,4439.98) 5586.85,4458.09 ccw(c5586.85,4439.98) 5574.05,4452.79 ; 5574.05,4452.79 ccw(c5561.24,4465.59) 5579.35,4465.59 cw(c5561.24,4465.59) 5574.05,4452.79 ; 5574.05,4492.16 cw(c5586.85,4479.35) 5586.85,4497.46 ccw(c5586.85,4479.35) 5574.05,4492.16 ; 5574.05,4492.16 ccw(c5561.24,4504.96) 5579.35,4504.96 cw(c5561.24,4504.96) 5574.05,4492.16 ; 5574.05,4531.53 cw(c5586.85,4518.72) 5586.85,4536.83 ccw(c5586.85,4518.72) 5574.05,4531.53 ; 5574.05,4531.53 ccw(c5561.24,4544.33) 5579.35,4544.33 cw(c5561.24,4544.33) 5574.05,4531.53 ; 5613.42,3927.21 cw(c5600.61,3914.41) 5618.72,3914.41 ccw(c5600.61,3914.41) 5613.42,3927.21 ; 5613.42,3927.21 ccw(c5626.22,3940.02) 5626.22,3921.91 cw(c5626.22,3940.02) 5613.42,3927.21 ; 5613.42,4570.9 cw(c5626.22,4558.09) 5626.22,4576.2 ccw(c5626.22,4558.09) 5613.42,4570.9 ; 5613.42,4570.9 ccw(c5600.61,4583.7) 5618.72,4583.7 cw(c5600.61,4583.7) 5613.42,4570.9 ; 5652.79,4531.53 cw(c5665.59,4518.72) 5665.59,4536.83 ccw(c5665.59,4518.72) 5652.79,4531.53 ; 5652.79,4531.53 ccw(c5639.98,4544.33) 5658.09,4544.33 cw(c5639.98,4544.33) 5652.79,4531.53 ; 5731.53,3809.1 cw(c5718.72,3796.3) 5736.83,3796.3 ccw(c5718.72,3796.3) 5731.53,3809.1 ; 5731.53,3809.1 ccw(c5744.33,3821.91) 5744.33,3803.8 cw(c5744.33,3821.91) 5731.53,3809.1 ; 5770.9,4124.06 cw(c5758.09,4111.26) 5776.2,4111.26 ccw(c5758.09,4111.26) 5770.9,4124.06 ; 5770.9,4124.06 ccw(c5783.7,4136.87) 5783.7,4118.76 cw(c5783.7,4136.87) 5770.9,4124.06 ; 5770.9,4216.57 cw(c5783.7,4203.76) 5783.7,4221.87 ccw(c5783.7,4203.76) 5770.9,4216.57 ; 5770.9,4216.57 ccw(c5758.09,4229.37) 5776.2,4229.37 cw(c5758.09,4229.37) 5770.9,4216.57 ; 5770.9,4295.31 cw(c5783.7,4282.5) 5783.7,4300.61 ccw(c5783.7,4282.5) 5770.9,4295.31 ; 5770.9,4295.31 ccw(c5758.09,4308.11) 5776.2,4308.11 cw(c5758.09,4308.11) 5770.9,4295.31 ; 5770.9,4413.42 cw(c5783.7,4400.61) 5783.7,4418.72 ccw(c5783.7,4400.61) 5770.9,4413.42 ; 5770.9,4413.42 ccw(c5758.09,4426.22) 5776.2,4426.22 cw(c5758.09,4426.22) 5770.9,4413.42 ; 5776.55,3764.08 cw(c5749.2,3736.73) 5787.88,3736.73 ; 5776.55,3764.08 cw(c5749.2,3736.73) 5787.88,3736.73 ; 5776.55,3764.08 cw(c5789.08,3776.61) 5771.36,3776.61 ccw(c5789.08,3776.61) 5776.55,3764.08 ; 5776.55,3764.08 ccw(c5764.02,3751.55) 5764.02,3769.27 cw(c5764.02,3751.55) 5776.55,3764.08 ; 5787.88,3736.73 5787.88,3670 5787.88,3736.73 ; 5815.92,4340.33 cw(c5843.27,4312.98) 5843.27,4351.66 ; 5815.92,4340.33 cw(c5843.27,4312.98) 5843.27,4351.66 ; 5815.92,4340.33 ccw(c5828.45,4327.8) 5810.73,4327.8 cw(c5828.45,4327.8) 5815.92,4340.33 ; 5815.92,4340.33 cw(c5803.39,4352.86) 5803.39,4335.14 ccw(c5803.39,4352.86) 5815.92,4340.33 ; 5815.92,4655.29 ccw(c5808.74,4662.47) 5818.89,4662.47 ; 5815.92,4655.29 ccw(c5808.74,4662.47) 5818.89,4662.47 ; 5815.92,4655.29 cw(c5803.39,4667.83) 5803.39,4650.1 ccw(c5803.39,4667.83) 5815.92,4655.29 ; 5815.92,4655.29 ccw(c5828.45,4642.76) 5810.73,4642.76 cw(c5828.45,4642.76) 5815.92,4655.29 ; 5818.89,4662.47 5818.89,4710 5818.89,4662.47 ; 5843.27,4351.66 5910,4351.66 5843.27,4351.66 ; 5855.29,4039.67 ccw(c5862.47,4046.85) 5862.47,4036.7 ; 5855.29,4039.67 ccw(c5862.47,4046.85) 5862.47,4036.7 ; 5855.29,4039.67 ccw(c5842.76,4027.14) 5842.76,4044.86 cw(c5842.76,4027.14) 5855.29,4039.67 ; 5855.29,4039.67 cw(c5867.83,4052.2) 5850.1,4052.2 ccw(c5867.83,4052.2) 5855.29,4039.67 ; 5855.29,4458.44 cw(c5862.47,4451.26) 5862.47,4461.41 ; 5855.29,4458.44 cw(c5862.47,4451.26) 5862.47,4461.41 ; 5855.29,4458.44 ccw(c5867.83,4445.91) 5850.1,4445.91 cw(c5867.83,4445.91) 5855.29,4458.44 ; 5855.29,4458.44 cw(c5842.76,4470.97) 5842.76,4453.25 ccw(c5842.76,4470.97) 5855.29,4458.44 ; 5855.29,4655.29 ccw(c5848.11,4662.47) 5858.26,4662.47 ; 5855.29,4655.29 ccw(c5848.11,4662.47) 5858.26,4662.47 ; 5855.29,4655.29 cw(c5842.76,4667.83) 5842.76,4650.1 ccw(c5842.76,4667.83) 5855.29,4655.29 ; 5855.29,4655.29 ccw(c5867.83,4642.76) 5850.1,4642.76 cw(c5867.83,4642.76) 5855.29,4655.29 ; 5858.26,4662.47 5858.26,4710 5858.26,4662.47 ; 5862.47,4036.7 5910,4036.7 5862.47,4036.7 ; 5862.47,4461.41 5910,4461.41 5862.47,4461.41 ; 5899.85,4052.2 cw(c5899.85,4069.93) 5887.32,4057.4 ccw(c5899.85,4069.93) 5899.85,4052.2 ; 5899.85,4052.2 ccw(c5899.85,4034.48) 5887.32,4047.01 cw(c5899.85,4034.48) 5899.85,4052.2 ; 5899.85,4445.91 cw(c5899.85,4463.63) 5887.32,4451.1 ccw(c5899.85,4463.63) 5899.85,4445.91 ; 5899.85,4445.91 ccw(c5899.85,4428.18) 5887.32,4440.71 cw(c5899.85,4428.18) 5899.85,4445.91 ; 5900.23,4052.2 cw(c5900.23,4070.31) 5887.43,4057.51 ccw(c5900.23,4070.31) 5900.23,4052.2 ; 5900.23,4052.2 ccw(c5900.23,4034.1) 5887.43,4046.9 cw(c5900.23,4034.1) 5900.23,4052.2 ; 5900.23,4445.91 cw(c5900.23,4464.01) 5887.43,4451.21 ccw(c5900.23,4464.01) 5900.23,4445.91 ; 5900.23,4445.91 ccw(c5900.23,4427.8) 5887.43,4440.6 cw(c5900.23,4427.8) 5900.23,4445.91 ; 5527.8,4682.13 5527.8,4710 5527.8,4682.13 ; 5882.13,4052.2 5910,4052.2 5882.13,4052.2 ; 5882.13,4445.91 5910,4445.91 5882.13,4445.91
